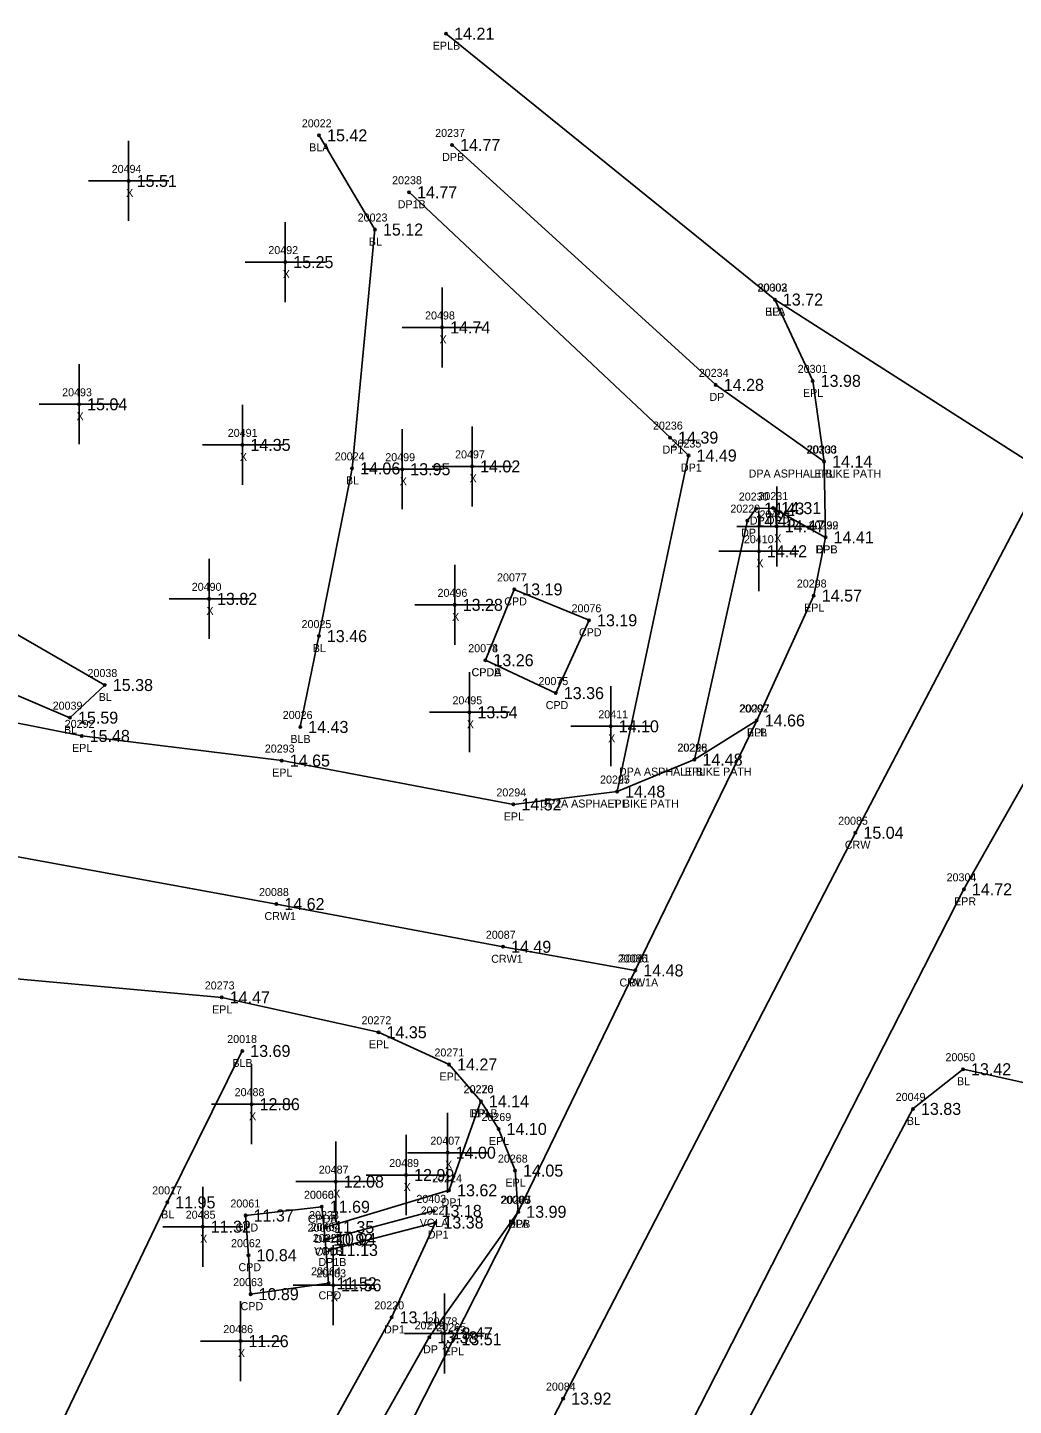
# Model space of a CAD drawing. Extents: x 2072302 to 2072980, y 127650 to 129736.
# Drawn here: x 2072759.7 to 2072882.9, y 128531.6 to 128703.8 of the extents above; entities that cross this region are included whole.
import ezdxf

# ---------------------------------------------------------------- set-up
doc = ezdxf.new("R2010")
doc.units = 0
for name, color, linetype in [('RD_DTM_BkLn1', 7, 'Continuous'), ('RD_DTM_BkLn_txCode', 7, 'Continuous'), ('RD_EX_Conc', 7, 'Continuous'), ('RD_EX_Conc_txCode', 7, 'Continuous'), ('RD_EX_Driveway', 7, 'Continuous'), ('RD_EX_Driveway_txCode', 7, 'Continuous'), ('RD_EX_Misc', 7, 'Continuous'), ('RD_EX_Misc_txCode', 7, 'Continuous'), ('RD_EX_Road', 7, 'Continuous'), ('RD_EX_Road_txCode', 7, 'Continuous'), ('RD_EX_TX_Conc_ELEV', 7, 'Continuous'), ('RD_EX_TX_Driveway_ELEV', 7, 'Continuous'), ('RD_EX_TX_Misc_ELEV', 7, 'Continuous'), ('RD_EX_TX_Road_ELEV', 7, 'Continuous'), ('RD_HC_Survey_ELEV', 7, 'Continuous'), ('RD_HC_Survey_txCode', 7, 'Continuous'), ('RD_SMD_Locator', 7, 'Continuous')]:
    doc.layers.add(name, color=color, linetype=linetype)

msp = doc.modelspace()

# ---------------------------------------------------------------- linework, layer by layer
at = {"layer": 'RD_DTM_BkLn1'}
for points in [[(2072796.13, 128690.3), (2072803.11, 128678.53), (2072800.25, 128648.68), (2072796.1, 128627.72), (2072793.77, 128616.37)], [(2072746.5, 128679.57), (2072744.56, 128635.92), (2072769.36, 128621.61), (2072765.01, 128617.53), (2072745.24, 128625.91)], [(2072853.07, 128669.78), (2072886.77, 128648.23), (2072918.79, 128632.23)], [(2072783.68, 128341.98), (2072775.38, 128381.91), (2072773.13, 128410.46), (2072778.13, 128436.13), (2072789.72, 128460.89), (2072826.62, 128532.44), (2072863.13, 128603.15), (2072886.77, 128648.23), (2072893.1, 128661.91)], [(2072821.01, 128555.78), (2072835.63, 128585.94), (2072850.8, 128617.18)], [(2072835.63, 128585.94), (2072819.11, 128588.9), (2072790.79, 128594.24), (2072731.84, 128605)], [(2072717.23, 128356.49), (2072726.05, 128417.31), (2072734.38, 128449.46), (2072744.93, 128479.47), (2072775.22, 128496.41), (2072780.14, 128517.18), (2072757.78, 128516.55), (2072777.16, 128556.96), (2072786.53, 128575.88)], [(2072791.29, 128345.62), (2072800.72, 128429.53), (2072808.9, 128452.58), (2072870.32, 128568.64), (2072876.57, 128573.6), (2072916.77, 128564.68), (2072920.97, 128548.67)]]:
    msp.add_lwpolyline(points, dxfattribs=at)
at = {"layer": 'RD_EX_Conc'}
for points in [[(2072816.91, 128624.71), (2072825.7, 128620.6), (2072829.85, 128629.7), (2072820.51, 128633.56), (2072816.91, 128624.71)], [(2072796.46, 128556.41), (2072786.95, 128555.32), (2072787.31, 128550.36), (2072787.57, 128545.49), (2072797.31, 128546.85), (2072796.87, 128552.3), (2072796.46, 128556.41)]]:
    msp.add_lwpolyline(points, dxfattribs=at)
at = {"layer": 'RD_EX_Driveway'}
for points in [[(2072859.22, 128649.54), (2072845.68, 128659.12), (2072812.75, 128689.1)], [(2072833.35, 128608.3), (2072842.28, 128650.29), (2072839.98, 128652.53), (2072807.37, 128683.19)], [(2072843.02, 128612.29), (2072849.63, 128642.15), (2072850.72, 128643.66), (2072852.84, 128643.72), (2072859.4, 128640.06)], [(2072797, 128553.87), (2072812.37, 128558.47), (2072816.34, 128569.6)], [(2072694.21, 128239.74), (2072695.7, 128289.15), (2072695.56, 128330.43), (2072696.37, 128337.85), (2072700.81, 128345.17), (2072711.22, 128347.96), (2072719.56, 128349.59), (2072725.15, 128351.26), (2072733.07, 128358.33), (2072734.19, 128365.42), (2072741.79, 128414.16), (2072748.82, 128445.27), (2072754.15, 128456.57), (2072759.92, 128465.41), (2072766.21, 128473.75), (2072780.47, 128491.8), (2072796.27, 128516), (2072809.9, 128540.1), (2072821.01, 128555.78)], [(2072689.37, 128239.9), (2072690.93, 128289.43), (2072690.32, 128330.24), (2072690.73, 128338.81), (2072697.63, 128350.77), (2072709.38, 128353.48), (2072719, 128355.15), (2072723.52, 128356.83), (2072727.18, 128360.82), (2072729.07, 128366.04), (2072736.87, 128415.65), (2072743.44, 128446.63), (2072749.73, 128459.37), (2072755.76, 128468.63), (2072761.76, 128476.56), (2072776.61, 128495.01), (2072792.09, 128518.96), (2072805.19, 128542.59), (2072810.66, 128554.44), (2072797.46, 128551.01)]]:
    msp.add_lwpolyline(points, dxfattribs=at)
at = {"layer": 'RD_EX_Misc'}
for p, q in [((2072772.34, 128679.61), (2072772.34, 128689.61)), ((2072767.34, 128684.61), (2072777.34, 128684.61)), ((2072791.9, 128669.46), (2072791.9, 128679.46)), ((2072786.9, 128674.46), (2072796.9, 128674.46)), ((2072811.49, 128661.29), (2072811.49, 128671.29)), ((2072806.49, 128666.29), (2072816.49, 128666.29)), ((2072766.15, 128651.69), (2072766.15, 128661.69)), ((2072761.15, 128656.69), (2072771.15, 128656.69)), ((2072786.55, 128646.62), (2072786.55, 128656.62)), ((2072806.52, 128643.58), (2072806.52, 128653.58)), ((2072815.24, 128643.93), (2072815.24, 128653.93)), ((2072781.55, 128651.62), (2072791.55, 128651.62)), ((2072801.52, 128648.58), (2072811.52, 128648.58)), ((2072810.24, 128648.93), (2072820.24, 128648.93)), ((2072853.3, 128636.43), (2072853.3, 128646.43)), ((2072851.07, 128633.33), (2072851.07, 128643.33)), ((2072848.3, 128641.43), (2072858.3, 128641.43)), ((2072782.38, 128627.38), (2072782.38, 128637.38)), ((2072846.07, 128638.33), (2072856.07, 128638.33)), ((2072813.07, 128626.63), (2072813.07, 128636.63)), ((2072777.38, 128632.38), (2072787.38, 128632.38)), ((2072808.07, 128631.63), (2072818.07, 128631.63)), ((2072814.91, 128613.2), (2072814.91, 128623.2)), ((2072832.56, 128611.45), (2072832.56, 128621.45)), ((2072809.91, 128618.2), (2072819.91, 128618.2)), ((2072827.56, 128616.45), (2072837.56, 128616.45)), ((2072787.7, 128564.23), (2072787.7, 128574.23)), ((2072782.7, 128569.23), (2072792.7, 128569.23)), ((2072812.19, 128558.17), (2072812.19, 128568.17)), ((2072807, 128555.38), (2072807, 128565.38)), ((2072798.21, 128554.55), (2072798.21, 128564.55)), ((2072807.19, 128563.17), (2072817.19, 128563.17)), ((2072802, 128560.38), (2072812, 128560.38)), ((2072781.59, 128548.92), (2072781.59, 128558.92)), ((2072793.21, 128559.55), (2072803.21, 128559.55)), ((2072776.59, 128553.92), (2072786.59, 128553.92)), ((2072797.9, 128541.6), (2072797.9, 128551.6)), ((2072792.9, 128546.6), (2072802.9, 128546.6)), ((2072786.31, 128534.62), (2072786.31, 128544.62)), ((2072811.81, 128535.59), (2072811.81, 128545.59)), ((2072781.31, 128539.62), (2072791.31, 128539.62)), ((2072806.81, 128540.59), (2072816.81, 128540.59))]:
    msp.add_line(p, q, dxfattribs=at)
at = {"layer": 'RD_EX_Road'}
msp.add_line((2072810.43, 128555.9), (2072797.24, 128552.38), dxfattribs=at)
for points in [[(2072734.64, 128675.72), (2072738.84, 128675.55), (2072739.33, 128643.18), (2072740.56, 128632.37), (2072745.62, 128623.39), (2072752.36, 128618.05), (2072766.47, 128615.25), (2072791.47, 128612.17), (2072820.4, 128606.69), (2072833.35, 128608.3), (2072843.02, 128612.29), (2072850.8, 128617.18), (2072857.93, 128632.79), (2072859.4, 128640.06), (2072859.22, 128649.54), (2072857.79, 128659.62), (2072853.07, 128669.78), (2072812, 128703)], [(2072789.45, 128345.69), (2072789.46, 128382.93), (2072788.01, 128408.09), (2072794.06, 128431.26), (2072804.3, 128453.88), (2072840.7, 128525.64), (2072876.68, 128596.08), (2072888.72, 128617.36), (2072893.24, 128622.62), (2072899.84, 128627.36), (2072910.72, 128631.76), (2072918.79, 128632.23), (2072935.82, 128627.02), (2072957.37, 128619.98)], [(2072775.68, 128466.69), (2072812.91, 128539.86), (2072821.01, 128555.78), (2072820.61, 128560.93), (2072818.55, 128566.13), (2072816.34, 128569.6), (2072812.37, 128574.19), (2072803.55, 128578.22), (2072783.97, 128582.57), (2072748.23, 128585.83), (2072732.11, 128585.24), (2072729.74, 128580.26), (2072735.29, 128576), (2072744.65, 128575.04), (2072744.47, 128530.69)]]:
    msp.add_lwpolyline(points, dxfattribs=at)
at = {"layer": 'RD_SMD_Locator'}
for centre in [(2072812, 128703), (2072796.13, 128690.3), (2072812.75, 128689.1), (2072772.34, 128684.61), (2072807.37, 128683.19), (2072803.11, 128678.53), (2072791.9, 128674.46), (2072853.07, 128669.78), (2072853.07, 128669.78), (2072811.49, 128666.29), (2072857.79, 128659.62), (2072845.68, 128659.12), (2072766.15, 128656.69), (2072786.55, 128651.62), (2072839.98, 128652.53), (2072842.28, 128650.29), (2072859.22, 128649.54), (2072859.22, 128649.54), (2072800.25, 128648.68), (2072806.52, 128648.58), (2072815.24, 128648.93), (2072850.72, 128643.66), (2072852.84, 128643.72), (2072849.63, 128642.15), (2072853.3, 128641.43), (2072859.4, 128640.06), (2072859.4, 128640.06), (2072851.07, 128638.33), (2072782.38, 128632.38), (2072820.51, 128633.56), (2072857.93, 128632.79), (2072813.07, 128631.63), (2072829.85, 128629.7), (2072796.1, 128627.72), (2072816.91, 128624.71), (2072816.91, 128624.71), (2072769.36, 128621.61), (2072825.7, 128620.6), (2072814.91, 128618.2), (2072765.01, 128617.53), (2072832.56, 128616.45), (2072850.8, 128617.18), (2072850.8, 128617.18), (2072766.47, 128615.25), (2072793.77, 128616.37), (2072791.47, 128612.17), (2072843.02, 128612.29), (2072843.02, 128612.29), (2072833.35, 128608.3), (2072833.35, 128608.3), (2072820.4, 128606.69), (2072863.13, 128603.15), (2072876.68, 128596.08), (2072790.79, 128594.24), (2072819.11, 128588.9), (2072835.63, 128585.94), (2072835.63, 128585.94), (2072783.97, 128582.57), (2072803.55, 128578.22), (2072786.53, 128575.88), (2072812.37, 128574.19), (2072876.57, 128573.6), (2072787.7, 128569.23), (2072816.34, 128569.6), (2072816.34, 128569.6), (2072870.32, 128568.64), (2072818.55, 128566.13), (2072812.19, 128563.17), (2072807, 128560.38), (2072820.61, 128560.93), (2072798.21, 128559.55), (2072812.37, 128558.47), (2072777.16, 128556.96), (2072796.46, 128556.41), (2072796.46, 128556.41), (2072786.95, 128555.32), (2072810.43, 128555.9), (2072810.66, 128554.44), (2072821.01, 128555.78), (2072821.01, 128555.78), (2072821.01, 128555.78), (2072781.59, 128553.92), (2072797, 128553.87), (2072796.87, 128552.3), (2072797.24, 128552.38), (2072797.46, 128551.01), (2072787.31, 128550.36), (2072797.31, 128546.85), (2072797.9, 128546.6), (2072787.57, 128545.49), (2072805.19, 128542.59), (2072786.31, 128539.62), (2072809.9, 128540.1), (2072811.81, 128540.59), (2072812.91, 128539.86), (2072826.62, 128532.44)]:
    msp.add_circle(centre, 0.15, dxfattribs=at)

# ---------------------------------------------------------------- texts
at = {"layer": 'RD_DTM_BkLn_txCode'}
for s, p in [('20022', (2072793.97, 128691.3)), ('BLA', (2072794.89, 128688.3)), ('20023', (2072800.95, 128679.53)), ('BL', (2072802.35, 128676.53)), ('20003', (2072850.88, 128670.78)), ('BLA', (2072851.83, 128667.78)), ('20024', (2072798.09, 128649.68)), ('BL', (2072799.49, 128646.68)), ('20025', (2072793.94, 128628.72)), ('BL', (2072795.34, 128625.72)), ('20038', (2072767.2, 128622.61)), ('BL', (2072768.6, 128619.61)), ('20039', (2072762.85, 128618.53)), ('20026', (2072791.59, 128617.37)), ('20002', (2072848.6, 128618.18)), ('BL', (2072764.26, 128615.53)), ('BLB', (2072792.54, 128614.37)), ('BLB', (2072849.57, 128615.18)), ('20001', (2072833.71, 128586.94)), ('BL', (2072834.87, 128583.94)), ('20018', (2072784.65, 128576.88)), ('20050', (2072874.38, 128574.6)), ('BLB', (2072785.3, 128573.88)), ('BL', (2072875.82, 128571.6)), ('20049', (2072868.16, 128569.64)), ('BL', (2072869.56, 128566.64)), ('20017', (2072775.28, 128557.96)), ('20000', (2072818.77, 128556.78)), ('BL', (2072776.4, 128554.96)), ('BLA', (2072819.77, 128553.78))]:
    msp.add_text(s, height=1, dxfattribs=at).set_placement(p)
at = {"layer": 'RD_EX_Conc_txCode'}
for s, p in [('20077', (2072818.36, 128634.56)), ('CPD', (2072819.26, 128631.56)), ('20076', (2072827.67, 128630.7)), ('CPD', (2072828.59, 128627.7)), ('20074', (2072814.76, 128625.71)), ('20078', (2072814.76, 128625.71)), ('CPDA', (2072815.17, 128622.71)), ('CPDB', (2072815.19, 128622.71)), ('20075', (2072823.54, 128621.6)), ('CPD', (2072824.44, 128618.6)), ('20060', (2072794.24, 128557.41)), ('20066', (2072794.25, 128557.41)), ('20061', (2072785.05, 128556.32)), ('CPDA', (2072794.72, 128554.41)), ('CPDB', (2072794.73, 128554.41)), ('CPD', (2072785.69, 128553.32)), ('20065', (2072794.69, 128553.3)), ('20062', (2072785.13, 128551.36)), ('CPD', (2072795.62, 128550.3)), ('CPD', (2072786.06, 128548.36)), ('20064', (2072795.13, 128547.85)), ('20063', (2072785.39, 128546.49)), ('CPD', (2072786.32, 128543.49)), ('CPD', (2072796.06, 128544.85))]:
    msp.add_text(s, height=1, dxfattribs=at).set_placement(p)
at = {"layer": 'RD_EX_Driveway_txCode'}
for s, p in [('20237', (2072810.63, 128690.1)), ('DPB', (2072811.5, 128687.1)), ('20238', (2072805.25, 128684.19)), ('DP1B', (2072805.95, 128681.19)), ('20234', (2072843.56, 128660.12)), ('DP', (2072844.9, 128657.12)), ('20236', (2072837.84, 128653.53)), ('DP1', (2072839.03, 128650.53)), ('20235', (2072840.16, 128651.29)), ('20233', (2072857.1, 128650.54)), ('DP1', (2072841.33, 128648.29)), ('DPA ASPHALT BIKE PATH', (2072849.79, 128647.54)), ('20229', (2072847.51, 128643.15)), ('20230', (2072848.56, 128644.66)), ('20231', (2072851.01, 128644.72)), ('DP', (2072849.94, 128641.66)), ('DP', (2072852.06, 128641.72)), ('DP', (2072848.85, 128640.15)), ('20232', (2072857.28, 128641.06)), ('DPB', (2072858.15, 128638.06)), ('20228', (2072840.91, 128613.29)), ('20227', (2072831.23, 128609.3)), ('DPA ASPHALT BIKE PATH', (2072833.59, 128610.29)), ('DP1A ASPHALT BIKE PATH', (2072823.75, 128606.3)), ('20226', (2072814.2, 128570.6)), ('DP1B', (2072814.92, 128567.6)), ('20224', (2072810.25, 128559.47)), ('20221', (2072808.82, 128555.44)), ('DP1', (2072811.43, 128556.47)), ('20225', (2072818.89, 128556.78)), ('20223', (2072794.88, 128554.87)), ('DPB', (2072819.76, 128553.78)), ('20222', (2072795.35, 128552.01)), ('DP1A', (2072795.57, 128551.87)), ('DP1', (2072809.71, 128552.44)), ('DP1B', (2072796.05, 128549.01)), ('20220', (2072803.03, 128543.59)), ('DP1', (2072804.24, 128540.59)), ('20219', (2072808.06, 128541.1)), ('DP', (2072809.12, 128538.1))]:
    msp.add_text(s, height=1, dxfattribs=at).set_placement(p)
at = {"layer": 'RD_EX_Misc_txCode'}
for s, p in [('20494', (2072770.22, 128685.61)), ('X', (2072772.03, 128682.61)), ('20492', (2072789.79, 128675.46)), ('X', (2072791.59, 128672.46)), ('20498', (2072809.37, 128667.29)), ('X', (2072811.17, 128664.29)), ('20493', (2072764.03, 128657.69)), ('X', (2072765.83, 128654.69)), ('20491', (2072784.72, 128652.62)), ('X', (2072786.24, 128649.62)), ('20499', (2072804.4, 128649.58)), ('20497', (2072813.12, 128649.93)), ('X', (2072806.21, 128646.58)), ('X', (2072814.93, 128646.93)), ('20409', (2072851.15, 128642.43)), ('20410', (2072849.2, 128639.33)), ('X', (2072852.99, 128639.43)), ('X', (2072850.75, 128636.33)), ('20490', (2072780.22, 128633.38)), ('20496', (2072810.93, 128632.63)), ('X', (2072782.06, 128630.38)), ('X', (2072812.75, 128629.63)), ('20495', (2072812.79, 128619.2)), ('20411', (2072831.01, 128617.45)), ('X', (2072814.59, 128616.2)), ('X', (2072832.24, 128614.45)), ('20488', (2072785.58, 128570.23)), ('X', (2072787.38, 128567.23)), ('20407', (2072810.03, 128564.17)), ('20487', (2072796.09, 128560.55)), ('20489', (2072804.89, 128561.38)), ('X', (2072811.87, 128561.17)), ('X', (2072797.89, 128557.55)), ('X', (2072806.69, 128558.38)), ('20485', (2072779.47, 128554.92)), ('X', (2072781.27, 128551.92)), ('20483', (2072795.78, 128547.6)), ('X', (2072797.59, 128544.6)), ('20478', (2072809.69, 128541.59)), ('20486', (2072784.16, 128540.62)), ('X', (2072811.49, 128538.59)), ('X', (2072785.99, 128537.62))]:
    msp.add_text(s, height=1, dxfattribs=at).set_placement(p)
at = {"layer": 'RD_EX_Road_txCode'}
for s, p in [('EPLB', (2072810.33, 128701)), ('20302', (2072850.92, 128670.78)), ('EPL', (2072851.87, 128667.78)), ('20301', (2072855.92, 128660.62)), ('EPL', (2072856.58, 128657.62)), ('20300', (2072857.02, 128650.54)), ('EPL', (2072858.01, 128647.54)), ('20299', (2072857.28, 128641.06)), ('EPL', (2072858.2, 128638.06)), ('20298', (2072855.81, 128633.79)), ('EPL', (2072856.72, 128630.79)), ('20297', (2072848.68, 128618.18)), ('20292', (2072764.35, 128616.25)), ('EPL', (2072849.59, 128615.18)), ('EPL', (2072765.27, 128613.25)), ('20293', (2072789.35, 128613.17)), ('20296', (2072840.88, 128613.29)), ('EPL', (2072790.27, 128610.17)), ('20295', (2072831.23, 128609.3)), ('EPL', (2072841.82, 128610.29)), ('20294', (2072818.28, 128607.69)), ('EPL', (2072832.14, 128606.3)), ('EPL', (2072819.2, 128604.69)), ('20304', (2072874.52, 128597.08)), ('EPR', (2072875.45, 128594.08)), ('20273', (2072781.85, 128583.57)), ('EPL', (2072782.76, 128580.57)), ('20272', (2072801.43, 128579.22)), ('EPL', (2072802.35, 128576.22)), ('20271', (2072810.54, 128575.19)), ('EPL', (2072811.17, 128572.19)), ('20270', (2072814.18, 128570.6)), ('EPL', (2072815.14, 128567.6)), ('20269', (2072816.41, 128567.13)), ('EPL', (2072817.34, 128564.13)), ('20268', (2072818.47, 128561.93)), ('EPL', (2072819.41, 128558.93)), ('20403', (2072808.28, 128556.9)), ('20267', (2072818.87, 128556.78)), ('VGLA', (2072808.7, 128553.9)), ('EPL', (2072819.81, 128553.78)), ('20404', (2072795.08, 128553.38)), ('VGLB', (2072795.52, 128550.38)), ('20265', (2072810.77, 128540.86)), ('EPL', (2072811.71, 128537.86))]:
    msp.add_text(s, height=1, dxfattribs=at).set_placement(p)
at = {"layer": 'RD_EX_TX_Conc_ELEV'}
for s, p in [('13.19', (2072821.51, 128632.81)), ('13.19', (2072830.85, 128628.95)), ('13.26', (2072817.91, 128623.96)), ('13.26', (2072817.91, 128623.96)), ('13.36', (2072826.7, 128619.85)), ('11.69', (2072797.46, 128555.66)), ('11.69', (2072797.46, 128555.66)), ('11.37', (2072787.95, 128554.57)), ('10.92', (2072797.87, 128551.55)), ('10.84', (2072788.31, 128549.61)), ('10.89', (2072788.57, 128544.74)), ('11.52', (2072798.31, 128546.1))]:
    msp.add_text(s, height=1.5, dxfattribs=at).set_placement(p)
at = {"layer": 'RD_EX_TX_Driveway_ELEV'}
for s, p in [('14.77', (2072813.75, 128688.35)), ('14.77', (2072808.37, 128682.44)), ('14.28', (2072846.68, 128658.37)), ('14.39', (2072840.98, 128651.78)), ('14.49', (2072843.28, 128649.54)), ('14.14', (2072860.22, 128648.79)), ('14.43', (2072851.72, 128642.91)), ('14.31', (2072853.84, 128642.97)), ('14.45', (2072850.63, 128641.4)), ('14.41', (2072860.4, 128639.31)), ('14.48', (2072844.02, 128611.54)), ('14.48', (2072834.35, 128607.55)), ('14.14', (2072817.34, 128568.85)), ('13.62', (2072813.37, 128557.72)), ('13.99', (2072822.01, 128555.03)), ('11.35', (2072798, 128553.12)), ('13.38', (2072811.66, 128553.69)), ('11.13', (2072798.46, 128550.26)), ('13.11', (2072806.19, 128541.84)), ('13.38', (2072810.9, 128539.35))]:
    msp.add_text(s, height=1.5, dxfattribs=at).set_placement(p)
at = {"layer": 'RD_EX_TX_Misc_ELEV'}
for s, p in [('15.42', (2072797.13, 128689.55)), ('15.51', (2072773.34, 128683.86)), ('15.12', (2072804.11, 128677.78)), ('15.25', (2072792.9, 128673.71)), ('13.72', (2072854.07, 128669.03)), ('14.74', (2072812.49, 128665.54)), ('15.04', (2072767.15, 128655.94)), ('14.35', (2072787.55, 128650.87)), ('14.06', (2072801.25, 128647.93)), ('13.95', (2072807.52, 128647.83)), ('14.02', (2072816.24, 128648.18)), ('14.47', (2072854.3, 128640.68)), ('14.42', (2072852.07, 128637.58)), ('13.82', (2072783.38, 128631.63)), ('13.28', (2072814.07, 128630.88)), ('13.46', (2072797.1, 128626.97)), ('15.38', (2072770.36, 128620.86)), ('15.59', (2072766.01, 128616.78)), ('13.54', (2072815.91, 128617.45)), ('14.43', (2072794.77, 128615.62)), ('14.10', (2072833.56, 128615.7)), ('14.66', (2072851.8, 128616.43)), ('14.48', (2072836.63, 128585.19)), ('13.69', (2072787.53, 128575.13)), ('13.42', (2072877.57, 128572.85)), ('12.86', (2072788.7, 128568.48)), ('13.83', (2072871.32, 128567.89)), ('14.00', (2072813.19, 128562.42)), ('12.08', (2072799.21, 128558.8)), ('12.99', (2072808, 128559.63)), ('11.95', (2072778.16, 128556.21)), ('13.99', (2072822.01, 128555.03)), ('11.32', (2072782.59, 128553.17)), ('11.56', (2072798.9, 128545.85)), ('13.47', (2072812.81, 128539.84)), ('11.26', (2072787.31, 128538.87))]:
    msp.add_text(s, height=1.5, dxfattribs=at).set_placement(p)
at = {"layer": 'RD_EX_TX_Road_ELEV'}
for s, p in [('14.21', (2072813, 128702.25)), ('13.72', (2072854.07, 128669.03)), ('13.98', (2072858.79, 128658.87)), ('14.14', (2072860.22, 128648.79)), ('14.41', (2072860.4, 128639.31)), ('14.57', (2072858.93, 128632.04)), ('14.66', (2072851.8, 128616.43)), ('15.48', (2072767.47, 128614.5)), ('14.65', (2072792.47, 128611.42)), ('14.48', (2072844.02, 128611.54)), ('14.48', (2072834.35, 128607.55)), ('14.52', (2072821.4, 128605.94)), ('14.72', (2072877.68, 128595.33)), ('14.47', (2072784.97, 128581.82)), ('14.35', (2072804.55, 128577.47)), ('14.27', (2072813.37, 128573.44)), ('14.14', (2072817.34, 128568.85)), ('14.10', (2072819.55, 128565.38)), ('14.05', (2072821.61, 128560.18)), ('13.18', (2072811.43, 128555.15)), ('13.99', (2072822.01, 128555.03)), ('10.94', (2072798.24, 128551.63)), ('13.51', (2072813.91, 128539.11))]:
    msp.add_text(s, height=1.5, dxfattribs=at).set_placement(p)
at = {"layer": 'RD_HC_Survey_ELEV'}
for s, p in [('15.04', (2072864.13, 128602.4)), ('14.62', (2072791.79, 128593.49)), ('14.49', (2072820.11, 128588.15)), ('14.48', (2072836.63, 128585.19)), ('13.92', (2072827.62, 128531.69))]:
    msp.add_text(s, height=1.5, dxfattribs=at).set_placement(p)
at = {"layer": 'RD_HC_Survey_txCode'}
for s, p in [('20085', (2072860.97, 128604.15)), ('CRW', (2072861.81, 128601.15)), ('20088', (2072788.63, 128595.24)), ('CRW1', (2072789.31, 128592.24)), ('20087', (2072816.96, 128589.9)), ('CRW1', (2072817.63, 128586.9)), ('20086', (2072833.44, 128586.94)), ('CRW1A', (2072833.66, 128583.94)), ('20084', (2072824.47, 128533.44))]:
    msp.add_text(s, height=1, dxfattribs=at).set_placement(p)

doc.saveas('drawing.dxf')
